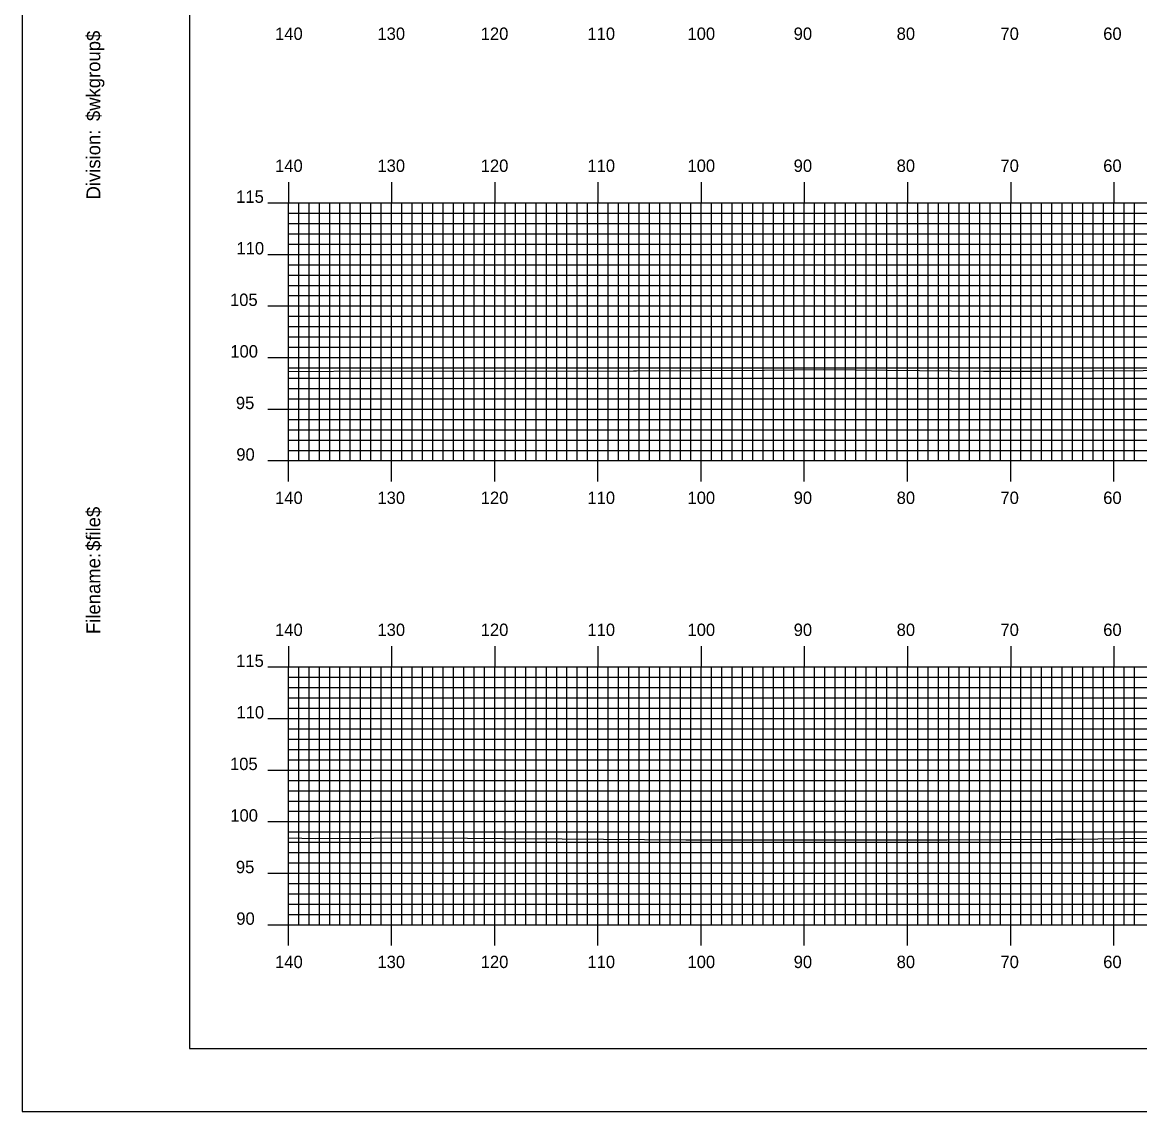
# Model space of a CAD drawing. Extents: x 1765333 to 1765676, y 442591 to 442811.
# Drawn here: x 1765332.6 to 1765440.9, y 442590.5 to 442696.2 of the extents above; entities that cross this region are included whole.
import ezdxf

# ---------------------------------------------------------------- set-up
doc = ezdxf.new("R2010")
doc.units = 0
for name, color, linetype in [('BORDER', 7, 'Continuous'), ('H_V ANNOTATION', 7, 'Continuous'), ('MAJOR', 7, 'Continuous'), ('MINOR', 7, 'Continuous'), ('PLOT BOUNDARY', 7, 'Continuous'), ('S_Roadway_Centerline', 7, 'Continuous')]:
    doc.layers.add(name, color=color, linetype=linetype)

msp = doc.modelspace()

# ---------------------------------------------------------------- linework, layer by layer
at = {"layer": 'BORDER'}
msp.add_lwpolyline([(1765348.77, 442596.67), (1765668.77, 442596.67), (1765668.77, 442806.67), (1765348.77, 442806.67)], close=True, dxfattribs=at)
at = {"layer": 'MAJOR'}
for p, q in [((1765358.37, 442680.67), (1765358.37, 442678.67)), ((1765368.37, 442680.67), (1765368.37, 442678.67)), ((1765378.37, 442680.67), (1765378.37, 442678.67)), ((1765388.37, 442680.67), (1765388.37, 442678.67)), ((1765398.37, 442680.67), (1765398.37, 442678.67)), ((1765408.37, 442680.67), (1765408.37, 442678.67)), ((1765418.37, 442680.67), (1765418.37, 442678.67)), ((1765428.37, 442680.67), (1765428.37, 442678.67)), ((1765438.37, 442680.67), (1765438.37, 442678.67)), ((1765356.37, 442678.67), (1765358.37, 442678.67)), ((1765358.37, 442678.67), (1765638.37, 442678.67)), ((1765358.37, 442653.67), (1765358.37, 442678.67)), ((1765358.37, 442653.67), (1765358.37, 442678.67)), ((1765358.37, 442678.67), (1765638.37, 442678.67)), ((1765368.37, 442653.67), (1765368.37, 442678.67)), ((1765378.37, 442653.67), (1765378.37, 442678.67)), ((1765388.37, 442653.67), (1765388.37, 442678.67)), ((1765398.37, 442653.67), (1765398.37, 442678.67)), ((1765408.37, 442653.67), (1765408.37, 442678.67)), ((1765418.37, 442653.67), (1765418.37, 442678.67)), ((1765428.37, 442653.67), (1765428.37, 442678.67)), ((1765438.37, 442653.67), (1765438.37, 442678.67)), ((1765356.37, 442673.67), (1765358.37, 442673.67)), ((1765358.37, 442673.67), (1765638.37, 442673.67)), ((1765356.37, 442668.67), (1765358.37, 442668.67)), ((1765358.37, 442668.67), (1765638.37, 442668.67)), ((1765356.37, 442663.67), (1765358.37, 442663.67)), ((1765358.37, 442663.67), (1765638.37, 442663.67)), ((1765356.37, 442658.67), (1765358.37, 442658.67)), ((1765358.37, 442658.67), (1765638.37, 442658.67)), ((1765356.37, 442653.67), (1765358.37, 442653.67)), ((1765358.37, 442653.67), (1765638.37, 442653.67)), ((1765358.37, 442653.67), (1765638.37, 442653.67)), ((1765358.37, 442651.66), (1765358.37, 442653.67)), ((1765368.37, 442651.66), (1765368.37, 442653.67)), ((1765378.37, 442651.66), (1765378.37, 442653.67)), ((1765388.37, 442651.66), (1765388.37, 442653.67)), ((1765398.37, 442651.66), (1765398.37, 442653.67)), ((1765408.37, 442651.66), (1765408.37, 442653.67)), ((1765418.37, 442651.66), (1765418.37, 442653.67)), ((1765428.37, 442651.66), (1765428.37, 442653.67)), ((1765438.37, 442651.66), (1765438.37, 442653.67)), ((1765358.37, 442635.67), (1765358.37, 442633.67)), ((1765368.37, 442635.67), (1765368.37, 442633.67)), ((1765378.37, 442635.67), (1765378.37, 442633.67)), ((1765388.37, 442635.67), (1765388.37, 442633.67)), ((1765398.37, 442635.67), (1765398.37, 442633.67)), ((1765408.37, 442635.67), (1765408.37, 442633.67)), ((1765418.37, 442635.67), (1765418.37, 442633.67)), ((1765428.37, 442635.67), (1765428.37, 442633.67)), ((1765438.37, 442635.67), (1765438.37, 442633.67)), ((1765356.37, 442633.67), (1765358.37, 442633.67)), ((1765358.37, 442633.67), (1765638.37, 442633.67)), ((1765358.37, 442608.67), (1765358.37, 442633.67)), ((1765358.37, 442608.67), (1765358.37, 442633.67)), ((1765358.37, 442633.67), (1765638.37, 442633.67)), ((1765368.37, 442608.67), (1765368.37, 442633.67)), ((1765378.37, 442608.67), (1765378.37, 442633.67)), ((1765388.37, 442608.67), (1765388.37, 442633.67)), ((1765398.37, 442608.67), (1765398.37, 442633.67)), ((1765408.37, 442608.67), (1765408.37, 442633.67)), ((1765418.37, 442608.67), (1765418.37, 442633.67)), ((1765428.37, 442608.67), (1765428.37, 442633.67)), ((1765438.37, 442608.67), (1765438.37, 442633.67)), ((1765356.37, 442628.67), (1765358.37, 442628.67)), ((1765358.37, 442628.67), (1765638.37, 442628.67)), ((1765356.37, 442623.67), (1765358.37, 442623.67)), ((1765358.37, 442623.67), (1765638.37, 442623.67)), ((1765356.37, 442618.67), (1765358.37, 442618.67)), ((1765358.37, 442618.67), (1765638.37, 442618.67)), ((1765356.37, 442613.67), (1765358.37, 442613.67)), ((1765358.37, 442613.67), (1765638.37, 442613.67)), ((1765356.37, 442608.67), (1765358.37, 442608.67)), ((1765358.37, 442608.67), (1765638.37, 442608.67)), ((1765358.37, 442608.67), (1765638.37, 442608.67)), ((1765358.37, 442606.66), (1765358.37, 442608.67)), ((1765368.37, 442606.66), (1765368.37, 442608.67)), ((1765378.37, 442606.66), (1765378.37, 442608.67)), ((1765388.37, 442606.66), (1765388.37, 442608.67)), ((1765398.37, 442606.66), (1765398.37, 442608.67)), ((1765408.37, 442606.66), (1765408.37, 442608.67)), ((1765418.37, 442606.66), (1765418.37, 442608.67)), ((1765428.37, 442606.66), (1765428.37, 442608.67)), ((1765438.37, 442606.66), (1765438.37, 442608.67))]:
    msp.add_line(p, q, dxfattribs=at)
at = {"layer": 'MINOR'}
for p, q in [((1765359.37, 442653.67), (1765359.37, 442678.67)), ((1765360.37, 442653.67), (1765360.37, 442678.67)), ((1765361.37, 442653.67), (1765361.37, 442678.67)), ((1765362.37, 442653.67), (1765362.37, 442678.67)), ((1765363.37, 442653.67), (1765363.37, 442678.67)), ((1765364.37, 442653.67), (1765364.37, 442678.67)), ((1765365.37, 442653.67), (1765365.37, 442678.67)), ((1765366.37, 442653.67), (1765366.37, 442678.67)), ((1765367.37, 442653.67), (1765367.37, 442678.67)), ((1765369.37, 442653.67), (1765369.37, 442678.67)), ((1765370.37, 442653.67), (1765370.37, 442678.67)), ((1765371.37, 442653.67), (1765371.37, 442678.67)), ((1765372.37, 442653.67), (1765372.37, 442678.67)), ((1765373.37, 442653.67), (1765373.37, 442678.67)), ((1765374.37, 442653.67), (1765374.37, 442678.67)), ((1765375.37, 442653.67), (1765375.37, 442678.67)), ((1765376.37, 442653.67), (1765376.37, 442678.67)), ((1765377.37, 442653.67), (1765377.37, 442678.67)), ((1765379.37, 442653.67), (1765379.37, 442678.67)), ((1765380.37, 442653.67), (1765380.37, 442678.67)), ((1765381.37, 442653.67), (1765381.37, 442678.67)), ((1765382.37, 442653.67), (1765382.37, 442678.67)), ((1765383.37, 442653.67), (1765383.37, 442678.67)), ((1765384.37, 442653.67), (1765384.37, 442678.67)), ((1765385.37, 442653.67), (1765385.37, 442678.67)), ((1765386.37, 442653.67), (1765386.37, 442678.67)), ((1765387.37, 442653.67), (1765387.37, 442678.67)), ((1765389.37, 442653.67), (1765389.37, 442678.67)), ((1765390.37, 442653.67), (1765390.37, 442678.67)), ((1765391.37, 442653.67), (1765391.37, 442678.67)), ((1765392.37, 442653.67), (1765392.37, 442678.67)), ((1765393.37, 442653.67), (1765393.37, 442678.67)), ((1765394.37, 442653.67), (1765394.37, 442678.67)), ((1765395.37, 442653.67), (1765395.37, 442678.67)), ((1765396.37, 442653.67), (1765396.37, 442678.67)), ((1765397.37, 442653.67), (1765397.37, 442678.67)), ((1765399.37, 442653.67), (1765399.37, 442678.67)), ((1765400.37, 442653.67), (1765400.37, 442678.67)), ((1765401.37, 442653.67), (1765401.37, 442678.67)), ((1765402.37, 442653.67), (1765402.37, 442678.67)), ((1765403.37, 442653.67), (1765403.37, 442678.67)), ((1765404.37, 442653.67), (1765404.37, 442678.67)), ((1765405.37, 442653.67), (1765405.37, 442678.67)), ((1765406.37, 442653.67), (1765406.37, 442678.67)), ((1765407.37, 442653.67), (1765407.37, 442678.67)), ((1765409.37, 442653.67), (1765409.37, 442678.67)), ((1765410.37, 442653.67), (1765410.37, 442678.67)), ((1765411.37, 442653.67), (1765411.37, 442678.67)), ((1765412.37, 442653.67), (1765412.37, 442678.67)), ((1765413.37, 442653.67), (1765413.37, 442678.67)), ((1765414.37, 442653.67), (1765414.37, 442678.67)), ((1765415.37, 442653.67), (1765415.37, 442678.67)), ((1765416.37, 442653.67), (1765416.37, 442678.67)), ((1765417.37, 442653.67), (1765417.37, 442678.67)), ((1765419.37, 442653.67), (1765419.37, 442678.67)), ((1765420.37, 442653.67), (1765420.37, 442678.67)), ((1765421.37, 442653.67), (1765421.37, 442678.67)), ((1765422.37, 442653.67), (1765422.37, 442678.67)), ((1765423.37, 442653.67), (1765423.37, 442678.67)), ((1765424.37, 442653.67), (1765424.37, 442678.67)), ((1765425.37, 442653.67), (1765425.37, 442678.67)), ((1765426.37, 442653.67), (1765426.37, 442678.67)), ((1765427.37, 442653.67), (1765427.37, 442678.67)), ((1765429.37, 442653.67), (1765429.37, 442678.67)), ((1765430.37, 442653.67), (1765430.37, 442678.67)), ((1765431.37, 442653.67), (1765431.37, 442678.67)), ((1765432.37, 442653.67), (1765432.37, 442678.67)), ((1765433.37, 442653.67), (1765433.37, 442678.67)), ((1765434.37, 442653.67), (1765434.37, 442678.67)), ((1765435.37, 442653.67), (1765435.37, 442678.67)), ((1765436.37, 442653.67), (1765436.37, 442678.67)), ((1765437.37, 442653.67), (1765437.37, 442678.67)), ((1765439.37, 442653.67), (1765439.37, 442678.67)), ((1765440.37, 442653.67), (1765440.37, 442678.67)), ((1765358.37, 442677.67), (1765638.37, 442677.67)), ((1765358.37, 442677.67), (1765360.37, 442677.67)), ((1765358.37, 442676.67), (1765638.37, 442676.67)), ((1765358.37, 442676.67), (1765360.37, 442676.67)), ((1765358.37, 442675.67), (1765638.37, 442675.67)), ((1765358.37, 442675.67), (1765360.37, 442675.67)), ((1765358.37, 442674.67), (1765638.37, 442674.67)), ((1765358.37, 442674.67), (1765360.37, 442674.67)), ((1765358.37, 442672.67), (1765638.37, 442672.67)), ((1765358.37, 442672.67), (1765360.37, 442672.67)), ((1765358.37, 442671.67), (1765638.37, 442671.67)), ((1765358.37, 442671.67), (1765360.37, 442671.67)), ((1765358.37, 442670.67), (1765638.37, 442670.67)), ((1765358.37, 442670.67), (1765360.37, 442670.67)), ((1765358.37, 442669.67), (1765638.37, 442669.67)), ((1765358.37, 442669.67), (1765360.37, 442669.67)), ((1765358.37, 442667.67), (1765638.37, 442667.67)), ((1765358.37, 442667.67), (1765360.37, 442667.67)), ((1765358.37, 442666.67), (1765638.37, 442666.67)), ((1765358.37, 442666.67), (1765360.37, 442666.67)), ((1765358.37, 442665.67), (1765638.37, 442665.67)), ((1765358.37, 442665.67), (1765360.37, 442665.67)), ((1765358.37, 442664.67), (1765638.37, 442664.67)), ((1765358.37, 442664.67), (1765360.37, 442664.67)), ((1765358.37, 442662.67), (1765638.37, 442662.67)), ((1765358.37, 442662.67), (1765360.37, 442662.67)), ((1765358.37, 442661.67), (1765638.37, 442661.67)), ((1765358.37, 442661.67), (1765360.37, 442661.67)), ((1765358.37, 442660.67), (1765638.37, 442660.67)), ((1765358.37, 442660.67), (1765360.37, 442660.67)), ((1765358.37, 442659.67), (1765638.37, 442659.67)), ((1765358.37, 442659.67), (1765360.37, 442659.67)), ((1765358.37, 442657.67), (1765638.37, 442657.67)), ((1765358.37, 442657.67), (1765360.37, 442657.67)), ((1765358.37, 442656.67), (1765638.37, 442656.67)), ((1765358.37, 442656.67), (1765360.37, 442656.67)), ((1765358.37, 442655.67), (1765638.37, 442655.67)), ((1765358.37, 442655.67), (1765360.37, 442655.67)), ((1765358.37, 442654.67), (1765638.37, 442654.67)), ((1765358.37, 442654.67), (1765360.37, 442654.67)), ((1765359.37, 442608.67), (1765359.37, 442633.67)), ((1765360.37, 442608.67), (1765360.37, 442633.67)), ((1765361.37, 442608.67), (1765361.37, 442633.67)), ((1765362.37, 442608.67), (1765362.37, 442633.67)), ((1765363.37, 442608.67), (1765363.37, 442633.67)), ((1765364.37, 442608.67), (1765364.37, 442633.67)), ((1765365.37, 442608.67), (1765365.37, 442633.67)), ((1765366.37, 442608.67), (1765366.37, 442633.67)), ((1765367.37, 442608.67), (1765367.37, 442633.67)), ((1765369.37, 442608.67), (1765369.37, 442633.67)), ((1765370.37, 442608.67), (1765370.37, 442633.67)), ((1765371.37, 442608.67), (1765371.37, 442633.67)), ((1765372.37, 442608.67), (1765372.37, 442633.67)), ((1765373.37, 442608.67), (1765373.37, 442633.67)), ((1765374.37, 442608.67), (1765374.37, 442633.67)), ((1765375.37, 442608.67), (1765375.37, 442633.67)), ((1765376.37, 442608.67), (1765376.37, 442633.67)), ((1765377.37, 442608.67), (1765377.37, 442633.67)), ((1765379.37, 442608.67), (1765379.37, 442633.67)), ((1765380.37, 442608.67), (1765380.37, 442633.67)), ((1765381.37, 442608.67), (1765381.37, 442633.67)), ((1765382.37, 442608.67), (1765382.37, 442633.67)), ((1765383.37, 442608.67), (1765383.37, 442633.67)), ((1765384.37, 442608.67), (1765384.37, 442633.67)), ((1765385.37, 442608.67), (1765385.37, 442633.67)), ((1765386.37, 442608.67), (1765386.37, 442633.67)), ((1765387.37, 442608.67), (1765387.37, 442633.67)), ((1765389.37, 442608.67), (1765389.37, 442633.67)), ((1765390.37, 442608.67), (1765390.37, 442633.67)), ((1765391.37, 442608.67), (1765391.37, 442633.67)), ((1765392.37, 442608.67), (1765392.37, 442633.67)), ((1765393.37, 442608.67), (1765393.37, 442633.67)), ((1765394.37, 442608.67), (1765394.37, 442633.67)), ((1765395.37, 442608.67), (1765395.37, 442633.67)), ((1765396.37, 442608.67), (1765396.37, 442633.67)), ((1765397.37, 442608.67), (1765397.37, 442633.67)), ((1765399.37, 442608.67), (1765399.37, 442633.67)), ((1765400.37, 442608.67), (1765400.37, 442633.67)), ((1765401.37, 442608.67), (1765401.37, 442633.67)), ((1765402.37, 442608.67), (1765402.37, 442633.67)), ((1765403.37, 442608.67), (1765403.37, 442633.67)), ((1765404.37, 442608.67), (1765404.37, 442633.67)), ((1765405.37, 442608.67), (1765405.37, 442633.67)), ((1765406.37, 442608.67), (1765406.37, 442633.67)), ((1765407.37, 442608.67), (1765407.37, 442633.67)), ((1765409.37, 442608.67), (1765409.37, 442633.67)), ((1765410.37, 442608.67), (1765410.37, 442633.67)), ((1765411.37, 442608.67), (1765411.37, 442633.67)), ((1765412.37, 442608.67), (1765412.37, 442633.67)), ((1765413.37, 442608.67), (1765413.37, 442633.67)), ((1765414.37, 442608.67), (1765414.37, 442633.67)), ((1765415.37, 442608.67), (1765415.37, 442633.67)), ((1765416.37, 442608.67), (1765416.37, 442633.67)), ((1765417.37, 442608.67), (1765417.37, 442633.67)), ((1765419.37, 442608.67), (1765419.37, 442633.67)), ((1765420.37, 442608.67), (1765420.37, 442633.67)), ((1765421.37, 442608.67), (1765421.37, 442633.67)), ((1765422.37, 442608.67), (1765422.37, 442633.67)), ((1765423.37, 442608.67), (1765423.37, 442633.67)), ((1765424.37, 442608.67), (1765424.37, 442633.67)), ((1765425.37, 442608.67), (1765425.37, 442633.67)), ((1765426.37, 442608.67), (1765426.37, 442633.67)), ((1765427.37, 442608.67), (1765427.37, 442633.67)), ((1765429.37, 442608.67), (1765429.37, 442633.67)), ((1765430.37, 442608.67), (1765430.37, 442633.67)), ((1765431.37, 442608.67), (1765431.37, 442633.67)), ((1765432.37, 442608.67), (1765432.37, 442633.67)), ((1765433.37, 442608.67), (1765433.37, 442633.67)), ((1765434.37, 442608.67), (1765434.37, 442633.67)), ((1765435.37, 442608.67), (1765435.37, 442633.67)), ((1765436.37, 442608.67), (1765436.37, 442633.67)), ((1765437.37, 442608.67), (1765437.37, 442633.67)), ((1765439.37, 442608.67), (1765439.37, 442633.67)), ((1765440.37, 442608.67), (1765440.37, 442633.67)), ((1765358.37, 442632.67), (1765638.37, 442632.67)), ((1765358.37, 442632.67), (1765360.37, 442632.67)), ((1765358.37, 442631.67), (1765638.37, 442631.67)), ((1765358.37, 442631.67), (1765360.37, 442631.67)), ((1765358.37, 442630.67), (1765638.37, 442630.67)), ((1765358.37, 442630.67), (1765360.37, 442630.67)), ((1765358.37, 442629.67), (1765638.37, 442629.67)), ((1765358.37, 442629.67), (1765360.37, 442629.67)), ((1765358.37, 442627.67), (1765638.37, 442627.67)), ((1765358.37, 442627.67), (1765360.37, 442627.67)), ((1765358.37, 442626.67), (1765638.37, 442626.67)), ((1765358.37, 442626.67), (1765360.37, 442626.67)), ((1765358.37, 442625.67), (1765638.37, 442625.67)), ((1765358.37, 442625.67), (1765360.37, 442625.67)), ((1765358.37, 442624.67), (1765638.37, 442624.67)), ((1765358.37, 442624.67), (1765360.37, 442624.67)), ((1765358.37, 442622.67), (1765638.37, 442622.67)), ((1765358.37, 442622.67), (1765360.37, 442622.67)), ((1765358.37, 442621.67), (1765638.37, 442621.67)), ((1765358.37, 442621.67), (1765360.37, 442621.67)), ((1765358.37, 442620.67), (1765638.37, 442620.67)), ((1765358.37, 442620.67), (1765360.37, 442620.67)), ((1765358.37, 442619.67), (1765638.37, 442619.67)), ((1765358.37, 442619.67), (1765360.37, 442619.67)), ((1765358.37, 442617.67), (1765638.37, 442617.67)), ((1765358.37, 442617.67), (1765360.37, 442617.67)), ((1765358.37, 442616.67), (1765638.37, 442616.67)), ((1765358.37, 442616.67), (1765360.37, 442616.67)), ((1765358.37, 442615.67), (1765638.37, 442615.67)), ((1765358.37, 442615.67), (1765360.37, 442615.67)), ((1765358.37, 442614.67), (1765638.37, 442614.67)), ((1765358.37, 442614.67), (1765360.37, 442614.67)), ((1765358.37, 442612.67), (1765638.37, 442612.67)), ((1765358.37, 442612.67), (1765360.37, 442612.67)), ((1765358.37, 442611.67), (1765638.37, 442611.67)), ((1765358.37, 442611.67), (1765360.37, 442611.67)), ((1765358.37, 442610.67), (1765638.37, 442610.67)), ((1765358.37, 442610.67), (1765360.37, 442610.67)), ((1765358.37, 442609.67), (1765638.37, 442609.67)), ((1765358.37, 442609.67), (1765360.37, 442609.67))]:
    msp.add_line(p, q, dxfattribs=at)
at = {"layer": 'PLOT BOUNDARY'}
msp.add_lwpolyline([(1765332.58, 442590.55), (1765672.58, 442590.55), (1765672.58, 442810.55), (1765332.58, 442810.55)], close=True, dxfattribs=at)
at = {"layer": 'S_Roadway_Centerline'}
for points in [[(1765358.37, 442662.32), (1765367.15, 442662.39), (1765374.27, 442662.36), (1765391.83, 442662.38), (1765392.03, 442662.38), (1765392.12, 442662.38), (1765404.47, 442662.46), (1765410.21, 442662.51), (1765425.74, 442662.36), (1765428.23, 442662.36), (1765429.2, 442662.35), (1765431.28, 442662.36), (1765446.18, 442662.44)], [(1765358.37, 442617.09), (1765360.95, 442617.05), (1765372.34, 442617.09), (1765379.12, 442617.02), (1765384.89, 442616.99), (1765396.88, 442616.89), (1765397.93, 442616.89), (1765414.69, 442616.92), (1765422.22, 442616.91), (1765432.73, 442616.96), (1765434.61, 442616.98), (1765439, 442617.02), (1765447.02, 442617.11)]]:
    msp.add_lwpolyline(points, dxfattribs=at)

# ---------------------------------------------------------------- texts
at = {"layer": 'BORDER'}
for s, p in [('$wkgroup$', (1765340.14, 442686.6)), ('Division:', (1765340.14, 442679)), ('$file$', (1765340.14, 442644.92)), ('Filename:', (1765340.14, 442636.86))]:
    msp.add_text(s, height=1.339, rotation=90, dxfattribs=at).set_placement(p)
at = {"layer": 'H_V ANNOTATION'}
for s, p in [('140', (1765357.08, 442694.47)), ('130', (1765367, 442694.47)), ('120', (1765377.01, 442694.47)), ('110', (1765387.35, 442694.47)), ('100', (1765397.05, 442694.47)), ('90', (1765407.34, 442694.47)), ('80', (1765417.32, 442694.47)), ('70', (1765427.38, 442694.47)), ('60', (1765437.34, 442694.47)), ('140', (1765357.08, 442681.67)), ('130', (1765367, 442681.67)), ('120', (1765377.01, 442681.67)), ('110', (1765387.35, 442681.67)), ('100', (1765397.05, 442681.67)), ('90', (1765407.34, 442681.67)), ('80', (1765417.32, 442681.67)), ('70', (1765427.38, 442681.67)), ('60', (1765437.34, 442681.67)), ('115', (1765353.31, 442678.67)), ('110', (1765353.34, 442673.67)), ('105', (1765352.71, 442668.67)), ('100', (1765352.74, 442663.67)), ('95', (1765353.28, 442658.67)), ('90', (1765353.32, 442653.67)), ('140', (1765357.08, 442649.47)), ('130', (1765367, 442649.47)), ('120', (1765377.01, 442649.47)), ('110', (1765387.35, 442649.47)), ('100', (1765397.05, 442649.47)), ('90', (1765407.34, 442649.47)), ('80', (1765417.32, 442649.47)), ('70', (1765427.38, 442649.47)), ('60', (1765437.34, 442649.47)), ('140', (1765357.08, 442636.67)), ('130', (1765367, 442636.67)), ('120', (1765377.01, 442636.67)), ('110', (1765387.35, 442636.67)), ('100', (1765397.05, 442636.67)), ('90', (1765407.34, 442636.67)), ('80', (1765417.32, 442636.67)), ('70', (1765427.38, 442636.67)), ('60', (1765437.34, 442636.67)), ('115', (1765353.31, 442633.67)), ('110', (1765353.34, 442628.67)), ('105', (1765352.71, 442623.67)), ('100', (1765352.74, 442618.67)), ('95', (1765353.28, 442613.67)), ('90', (1765353.32, 442608.67)), ('140', (1765357.08, 442604.47)), ('130', (1765367, 442604.47)), ('120', (1765377.01, 442604.47)), ('110', (1765387.35, 442604.47)), ('100', (1765397.05, 442604.47)), ('90', (1765407.34, 442604.47)), ('80', (1765417.32, 442604.47)), ('70', (1765427.38, 442604.47)), ('60', (1765437.34, 442604.47))]:
    msp.add_text(s, height=1.2, dxfattribs=at).set_placement(p)
at = {"layer": 'MAJOR'}
for p in [(1765358.36, 442653.67), (1765358.36, 442608.67)]:
    msp.add_text('-', height=0.012, dxfattribs=at).set_placement(p)

doc.saveas('drawing.dxf')
